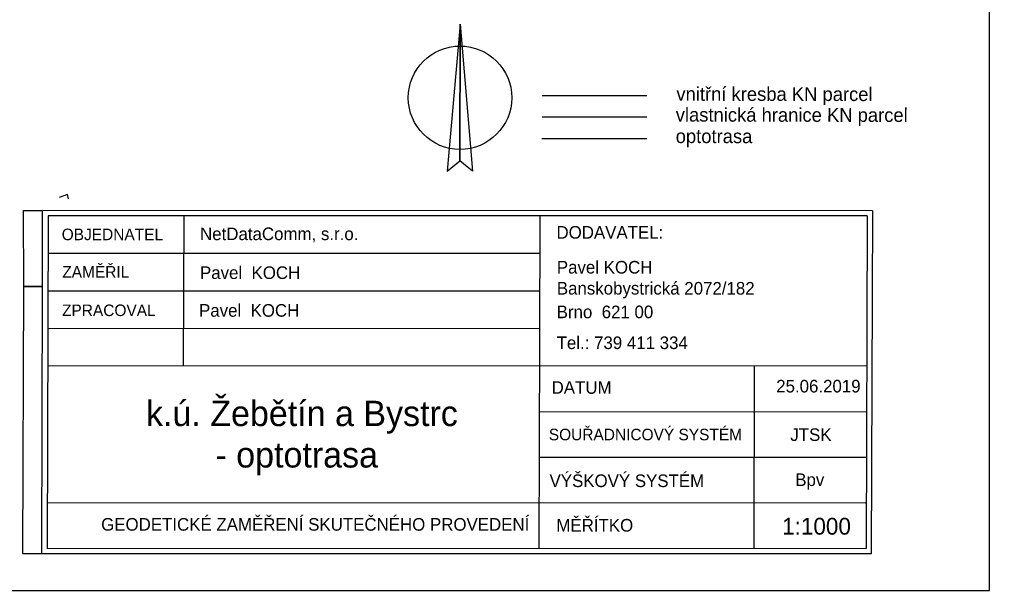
# Model space of a CAD drawing. Extents: x -606208 to -605570, y -1157873 to -1157573.
# Drawn here: x -605756.7 to -605573.3, y -1157873.5 to -1157765.4 of the extents above; entities that cross this region are included whole.
import ezdxf

# ---------------------------------------------------------------- set-up
doc = ezdxf.new("R2010")
doc.units = 0
for name, color, linetype in [('Vrstva 1', 7, 'Continuous'), ('Vrstva 62', 7, 'Continuous'), ('Vrstva 63', 7, 'Continuous')]:
    doc.layers.add(name, color=color, linetype=linetype)

msp = doc.modelspace()

# ---------------------------------------------------------------- linework, layer by layer
at = {"layer": 'Vrstva 1'}
msp.add_lwpolyline([(-606203.28, -1157873.46), (-605573.29, -1157873.46), (-605573.29, -1157576.47), (-606203.28, -1157576.47)], close=True, dxfattribs=at)
at = {"layer": 'Vrstva 62'}
for p, q in [((-605747.67, -1157798.52), (-605749.23, -1157799.08)), ((-605747.48, -1157799.33), (-605747.67, -1157798.52))]:
    msp.add_line(p, q, dxfattribs=at)
at = {"layer": 'Vrstva 63'}
for p, q in [((-605673.4, -1157766.3), (-605675.86, -1157794.11)), ((-605673.4, -1157766.3), (-605673.46, -1157792.12)), ((-605673.46, -1157792.12), (-605673.4, -1157766.3)), ((-605673.4, -1157766.3), (-605671.06, -1157794.12)), ((-605657.92, -1157779.78), (-605638.11, -1157779.79)), ((-605657.92, -1157783.84), (-605638.12, -1157783.85)), ((-605657.93, -1157787.9), (-605638.13, -1157787.91)), ((-605675.86, -1157794.11), (-605673.46, -1157792.12)), ((-605671.06, -1157794.12), (-605673.46, -1157792.12)), ((-605595.44, -1157801.59), (-605752.42, -1157801.56)), ((-605595.44, -1157801.59), (-605595.7, -1157866.5)), ((-605751.3, -1157802.57), (-605751.52, -1157865.53)), ((-605596.42, -1157802.58), (-605751.3, -1157802.57)), ((-605725.69, -1157830.98), (-605725.62, -1157802.57)), ((-605658.36, -1157826.19), (-605658.3, -1157802.57)), ((-605596.42, -1157802.58), (-605596.62, -1157865.51)), ((-605658.33, -1157809.69), (-605751.29, -1157809.69)), ((-605658.34, -1157816.83), (-605751.37, -1157816.79)), ((-605658.38, -1157823.91), (-605751.36, -1157823.9)), ((-605658.46, -1157865.55), (-605658.36, -1157826.19)), ((-605596.51, -1157830.94), (-605751.41, -1157830.97)), ((-605617.84, -1157865.54), (-605617.76, -1157830.99)), ((-605596.58, -1157839.67), (-605658.4, -1157839.63)), ((-605596.55, -1157848.3), (-605658.43, -1157848.3)), ((-605596.77, -1157856.91), (-605751.57, -1157856.87)), ((-605596.62, -1157865.51), (-605751.52, -1157865.53)), ((-605595.7, -1157866.5), (-605752.6, -1157866.5))]:
    msp.add_line(p, q, dxfattribs=at)
for points in [[(-605755.93, -1157815.92), (-605755.96, -1157801.56), (-605752.42, -1157801.56), (-605752.45, -1157815.9)], [(-605756.1, -1157866.52), (-605755.93, -1157815.92), (-605752.45, -1157815.9), (-605752.6, -1157866.5)]]:
    msp.add_lwpolyline(points, close=True, dxfattribs=at)
msp.add_circle((-605673.43, -1157780.21), 9.78, dxfattribs=at)

# ---------------------------------------------------------------- texts
for s, height, rotation, p in [('vnitřní kresba KN parcel', 2.6, 359.9083, (-605632.52, -1157780.78)), ('vlastnická hranice KN parcel', 2.6, 359.9083, (-605632.64, -1157784.72)), ('optotrasa', 2.6, 359.9083, (-605632.65, -1157788.78)), ('OBJEDNATEL', 2.186, 359.9959, (-605748.75, -1157807.16)), ('NetDataComm, s.r.o.', 2.3843, 359.9959, (-605722.59, -1157807.15)), ('DODAVATEL:', 2.384, 359.9959, (-605655.19, -1157806.87)), ('Pavel KOCH', 2.384, 359.9959, (-605655.12, -1157813.47)), ('ZAMĚŘIL', 2.186, 359.9959, (-605748.64, -1157814.24)), ('Pavel  KOCH', 2.3843, 359.9959, (-605722.6, -1157814.5)), ('Banskobystrická 2072/182', 2.3843, 359.9959, (-605655.12, -1157817.45)), ('ZPRACOVAL', 2.186, 359.9959, (-605748.69, -1157821.52)), ('Pavel  KOCH', 2.3843, 359.9959, (-605722.78, -1157821.64)), ('Brno  621 00', 2.3843, 359.9959, (-605655.15, -1157821.92)), ('Tel.: 739 411 334', 2.3843, 359.9959, (-605655.17, -1157827.76)), ('DATUM', 2.384, 359.9959, (-605656.11, -1157836.22)), ('25.06.2019', 2.384, 359.9959, (-605613.64, -1157835.97)), ('k.ú. Žebětín a Bystrc', 4.8083, 359.9959, (-605732.81, -1157842.33)), ('SOUŘADNICOVÝ SYSTÉM', 2.1856, 359.9959, (-605656.64, -1157845.02)), ('JTSK', 2.384, 359.9959, (-605610.97, -1157845.15)), ('- optotrasa', 4.8083, 359.9959, (-605719.68, -1157850.17)), ('VÝŠKOVÝ SYSTÉM', 2.3843, 359.9959, (-605656.5, -1157853.87)), ('Bpv', 2.384, 359.9959, (-605610.04, -1157853.67)), ('GEODETICKÉ ZAMĚŘENÍ SKUTEČNÉHO PROVEDENÍ', 2.3843, 359.9959, (-605741.29, -1157862.12)), ('MĚŘÍTKO', 2.384, 359.9959, (-605655.21, -1157862.29)), ('1:1000', 3.179, 359.9959, (-605612.52, -1157862.87))]:
    msp.add_text(s, height=height, rotation=rotation, dxfattribs=at).set_placement(p)

doc.saveas('drawing.dxf')
